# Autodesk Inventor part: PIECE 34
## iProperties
Created: 2004-11
Part Number: PIECE 34
Document SubType Name: Modeling
Designer: Bruno
Manufacturer: Standard
Standards Organization: Custom
Author: Bruno
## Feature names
1. Base1
